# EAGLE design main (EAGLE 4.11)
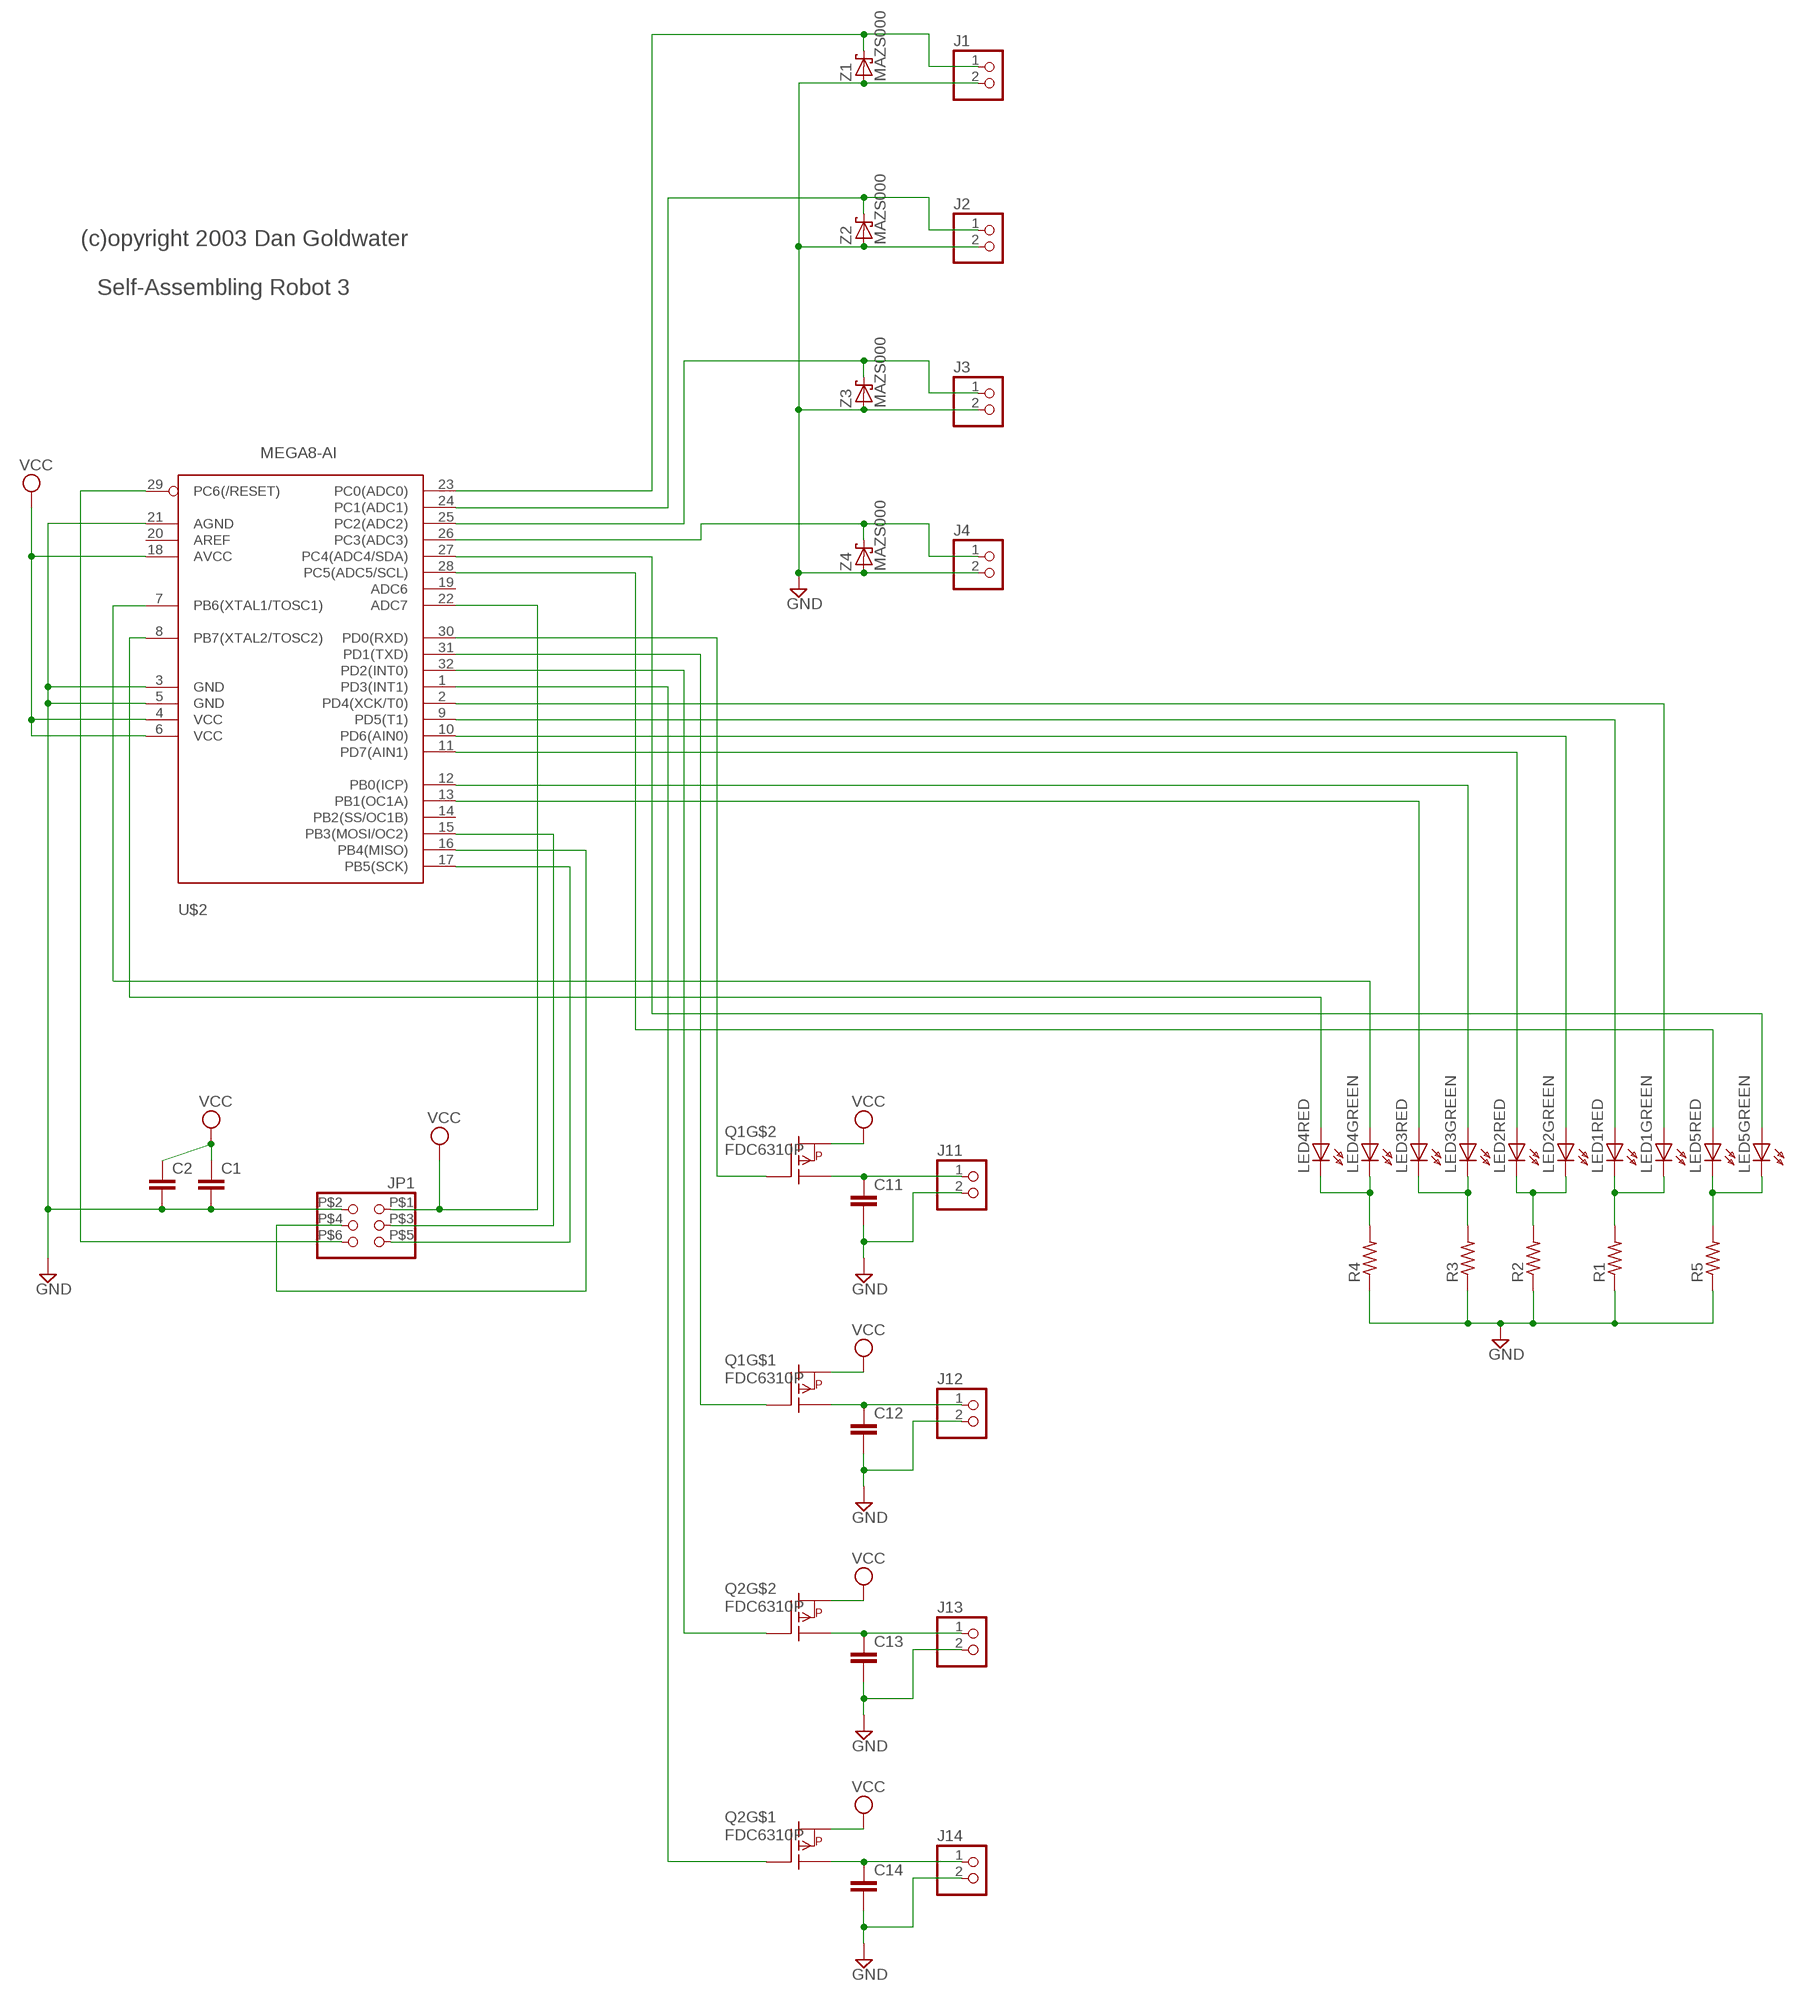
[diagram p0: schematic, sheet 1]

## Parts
C1  C-EUC0603  [C0603]
C2  C-EUC0603  [C0603]
C11  C-EUC0603  [C0603]
C12  C-EUC0603  [C0603]
C13  C-EUC0603  [C0603]
C14  C-EUC0603  [C0603]
J1  PINHD-1X2  [1X02]
J2  PINHD-1X2  [1X02]
J3  PINHD-1X2  [1X02]
J4  PINHD-1X2  [1X02]
J11  PINHD-1X2  [1X02]
J12  PINHD-1X2  [1X02]
J13  PINHD-1X2  [1X02]
J14  PINHD-1X2  [1X02]
JP1  PINHD-2X3SMT  [HIROSE_A3-6PA-2SV]
LED1  LTST-C195KGJRKT  [0605_4PIN]
LED2  LTST-C195KGJRKT  [0605_4PIN]
LED3  LTST-C195KGJRKT  [0605_4PIN]
LED4  LTST-C195KGJRKT  [0605_4PIN]
LED5  LTST-C195KGJRKT  [0605_4PIN]
Q1  FDC6310P  [SUPERSOT6]
Q2  FDC6310P  [SUPERSOT6]
R1  R-US_R0603  [R0603]
R2  R-US_R0603  [R0603]
R3  R-US_R0603  [R0603]
R4  R-US_R0603  [R0603]
R5  R-US_R0603  [R0603]
U$2  MEGA8-AI  [TQFP32-08]
Z1  MAZS000  [SSMINI2-F1]
Z2  MAZS000  [SSMINI2-F1]
Z3  MAZS000  [SSMINI2-F1]
Z4  MAZS000  [SSMINI2-F1]

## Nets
GND [power]: C1.2 C2.2 C11.2 C12.2 C13.2 C14.2 J1.2 J2.2 J3.2 J4.2 J11.2 J12.2 J13.2 J14.2 JP1.P$2 R1.1 R2.1 R3.1 R4.1 R5.1 U$2.3(GND) U$2.5(GND) U$2.21(AGND) Z1.A Z2.A Z3.A Z4.A
N$1: LED5.2(RED:A) U$2.28(PC5(ADC5/SCL))
N$2: J2.1 U$2.24(PC1(ADC1)) Z2.C
N$3: J3.1 U$2.25(PC2(ADC2)) Z3.C
N$4: J4.1 U$2.26(PC3(ADC3)) Z4.C
N$5: LED3.2(RED:A) U$2.13(PB1(OC1A))
N$6: JP1.P$6 U$2.29(PC6(/RESET))
N$7: JP1.P$5 U$2.17(PB5(SCK))
N$8: JP1.P$4 U$2.16(PB4(MISO))
N$9: C11.1 J11.1 Q1.4(DP)
N$10: Q1.3(GP) U$2.30(PD0(RXD))
N$11: LED2.3(GREEN:C) LED2.4(RED:C) R2.2
N$12: LED2.1(GREEN:A) U$2.10(PD6(AIN0))
N$13: LED1.2(RED:A) U$2.9(PD5(T1))
N$14: JP1.P$3 U$2.15(PB3(MOSI/OC2))
N$15: LED3.1(GREEN:A) U$2.12(PB0(ICP))
N$16: LED1.3(GREEN:C) LED1.4(RED:C) R1.2
N$17: LED4.3(GREEN:C) LED4.4(RED:C) R4.2
N$18: LED4.2(RED:A) U$2.8(PB7(XTAL2/TOSC2))
N$19: LED4.1(GREEN:A) U$2.7(PB6(XTAL1/TOSC1))
N$20: C12.1 J12.1 Q1.6(DP)
N$21: LED3.3(GREEN:C) LED3.4(RED:C) R3.2
N$22: C13.1 J13.1 Q2.4(DP)
N$23: LED2.2(RED:A) U$2.11(PD7(AIN1))
N$24: C14.1 J14.1 Q2.6(DP)
N$25: J1.1 U$2.23(PC0(ADC0)) Z1.C
N$26: LED5.1(GREEN:A) U$2.27(PC4(ADC4/SDA))
N$27: LED5.3(GREEN:C) LED5.4(RED:C) R5.2
N$28: Q1.1(GP) U$2.31(PD1(TXD))
N$29: Q2.3(GP) U$2.32(PD2(INT0))
N$30: Q2.1(GP) U$2.1(PD3(INT1))
N$31: LED1.1(GREEN:A) U$2.2(PD4(XCK/T0))
VCC [power]: C1.1 C2.1 JP1.P$1 Q1.2(SP) Q1.5(SP) Q2.2(SP) Q2.5(SP) U$2.4(VCC) U$2.6(VCC) U$2.18(AVCC) U$2.22(ADC7)
Unconnected: U$2.14(PB2(SS/OC1B)) U$2.19(ADC6) U$2.20(AREF)

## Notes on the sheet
- (c)opyright 2003 Dan Goldwater
- Self-Assembling Robot 3

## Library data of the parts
C1 C2 C11-C14 = proj:C-EU: CAPACITOR, European symbol
J1-J4 J11-J14 = proj:PINHD-1X2: 2mm PIN HEADER
JP1 = proj:PINHD-2X3: 2mm PIN HEADER
LED1-LED5 = proj:LTST-C195KGJRKT: Lite-On 0605 dual LED
Q1 Q2 = proj:FDC6310P
R1-R5 = proj:R-US_: RESISTOR, American symbol
U$2 = proj:MEGA8: MICROCONTROLLER 8 Kbytes FLASH 1 kbytes SRAM 512 bytes EEPROM USART 6-channel 10 bit ADC 2-channel 8 bit ADC
Z1-Z4 = proj:MAZS000: Panasonic Zener Diode

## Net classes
0 default: width 0.178 mm, drill 0.178 mm, clearance 0.381 mm
1 power: width 0.254 mm, drill 0.178 mm, clearance 0.381 mm

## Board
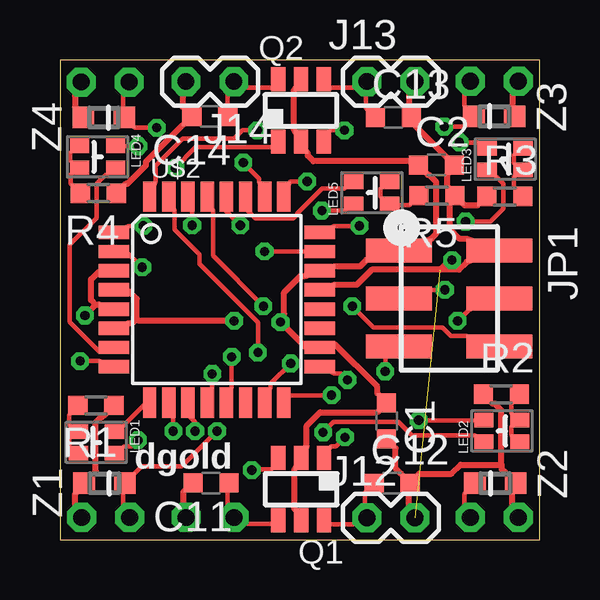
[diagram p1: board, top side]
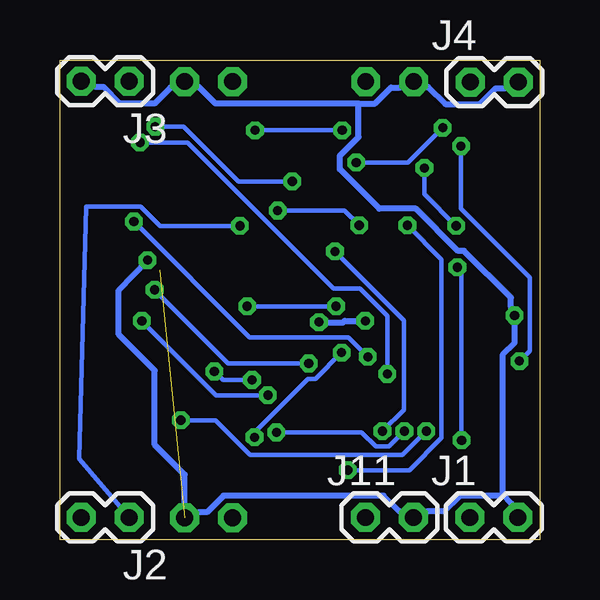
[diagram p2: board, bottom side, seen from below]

Size 20 x 20 mm. Coordinates in mm from the lower left corner, seen from the top.
Outline: 0,0 20,0 20,20 0,20 0,0
Copper layers (1*16): Top 0.035mm / dielectric 1.5mm / Bottom 0.035mm
Design rules "default": minimum track width 7mil, minimum drill 13mil, track to track 7mil, track to pad 7mil, pad to pad 7mil, via to via 7mil, smd to smd 5mil, copper to edge 10mil, drill to drill 7mil, minimum pad ring 10mil, minimum via ring 7mil, stop-mask expansion 0.5mil, vias tented up to drill 16mil, thermal gap 10mil

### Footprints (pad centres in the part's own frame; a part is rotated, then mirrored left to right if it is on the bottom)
C0603 = smd 0.8 x 0.8: 1 -0.75,0; 2 0.75,0
1X02 = drill 0.7 octagon: 1 -1,0; 2 1,0
HIROSE_A3-6PA-2SV = smd 1 x 2.75: P$1 -2,-2.1; P$2 -2,2.1; P$3 0,-2.1; P$4 0,2.1; P$5 2,-2.1; P$6 2,2.1
0605_4PIN = smd 0.6 x 0.8: 1 0.45,0.75; 2 -0.45,0.75; 3 0.45,-0.75; 4 -0.45,-0.75
SUPERSOT6 = smd 0.6 x 1: 1 -0.95,-1.3; 2 0,-1.3; 3 0.95,-1.3; 4 0.95,1.3; 5 0,1.3; 6 -0.95,1.3
R0603 = smd 0.8 x 0.8: 1 -0.75,0; 2 0.75,0
TQFP32-08 = smd 1.27 x 0.559: 1 -4.293,2.8; 2 -4.293,2; 3 -4.293,1.2; 4 -4.293,0.4; 5 -4.293,-0.4; 6 -4.293,-1.2; 7 -4.293,-2; 8 -4.293,-2.8; 17 4.293,-2.8; 18 4.293,-2; 19 4.293,-1.2; 20 4.293,-0.4; 21 4.293,0.4; 22 4.293,1.2; 23 4.293,2; 24 4.293,2.8 | smd 0.559 x 1.27: 9 -2.8,-4.293; 10 -2,-4.293; 11 -1.2,-4.293; 12 -0.4,-4.293; 13 0.4,-4.293; 14 1.2,-4.293; 15 2,-4.293; 16 2.8,-4.293; 25 2.8,4.293; 26 2,4.293; 27 1.2,4.293; 28 0.4,4.293; 29 -0.4,4.293; 30 -1.2,4.293; 31 -2,4.293; 32 -2.8,4.293
SSMINI2-F1 = smd 0.9 x 0.9: A 0,0.85; C 0,-0.85

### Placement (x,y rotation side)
C1  13.61,4.95 270 top
C2  15.7,15.61 0 top
C11  6.3,2.36 180 top
C12  13.85,2.35 0 top
C13  13.9,17.6 0 top
C14  6.25,17.65 180 top
J1  1.91,0.92 0 bottom
J2  18.11,0.92 180 bottom
J3  18.11,19.12 180 bottom
J4  1.89,19.08 0 bottom
J11  6.26,0.92 0 bottom
J12  13.8,0.9 0 top
J13  13.8,19.1 0 top
J14  6.25,19.1 180 top
JP1  16.23,10.06 270 top
LED1  1.52,4.05 270 top
LED2  18.43,4.53 90 top
LED3  18.56,15.86 90 top
LED4  1.57,15.96 270 top
LED5  13,14.46 90 top
Q1  10.06,2.1 180 top
Q2  10.05,17.9 0 top
R1  1.5,5.59 180 top
R2  18.4,6.06 0 top
R3  18.55,14.31 0 top
R4  1.6,14.44 180 top
R5  15.72,14.34 180 top
U$2  6.54,10.01 0 top
Z1  1.86,2.35 90 top
Z2  18.15,2.35 270 top
Z3  18.11,17.65 270 top
Z4  1.83,17.6 90 top

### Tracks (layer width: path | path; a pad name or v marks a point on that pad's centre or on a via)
GND  (via drill 0.38)  (1 unrouted)
  Top 0.254: U$2.21 11.46,10.62 12.37,10.62 13.01,11.25 16.64,11.25 16.97,11.58 JP1.P$2 16.97,12.55 16.66,12.55 16.23,12.98 16.23,13.95 R5.1 | Z4.A 0.64,18.03 0.64,18.49 J4.2 | R4.1 2.74,14.83 2.82,14.83 3.58,15.6 3.58,15.75 5.11,17.27 C14.2 5.11,18.03 5.11,18.52 J14.2 | Z3.A 18.87,18.09 18.87,18.52 J3.2 | R5.1 16.13,14.73 16.13,15.21 C2.2 16.05,16 14.83,17.22 C13.2 14.55,17.98 14.55,18.52 J13.2 | R3.1 17.42,13.95 16.87,13.95 R5.1 | C12.2 14.55,1.96 14.55,1.5 J12.2 | C1.2 13.99,3.81 13.99,2.97 14.22,2.74 C12.2 | 18.41,3.12 18.41,2.95 18.57,2.79 Z2.A 18.85,1.91 18.85,1.5 J2.2 | 18.41,3.12 18.41,5.38 18.14,5.66 18.03,5.66 R2.1 | C12.2 14.99,2.74 16.33,2.74 16.71,3.12 18.41,3.12 | C11.2 5.16,1.98 5.16,1.5 J11.2 | R1.1 1.85,5.21 1.75,5.11 1.73,5.11 1.5,4.88 1.5,2.85 1.45,2.79 Z1.A 0.64,1.91 0.64,1.5 J1.2 | 1.47,9.8 1.63,9.8 U$2.5 | 1.47,9.8 1.29,9.98 1.29,10.85 1.63,11.18 U$2.3 | v1.04,9.35 1.4,9.7 1.47,9.8 | v16.35,11.65 16.25,11.65 15.85,11.25
  Bottom 0.254: J4.2 1.47,18.82 1.83,18.82 2.49,18.16 3.94,18.16 4.65,18.87 J14.2 5.84,18.85 6.2,18.85 6.86,18.19 7.54,18.19 | J3.2 18.52,18.87 18.19,18.87 17.5,18.19 16.05,18.19 15.39,18.85 J13.2 14.2,18.87 13.51,18.19 7.54,18.19 | 1.52,1.85 1.52,7.72 1.04,8.2 v1.04,9.35 1.19,9.7 1.19,10.08 3.15,12.04 3.4,12.04 5.16,13.79 6.68,13.79 8.33,15.44 8.33,16 7.54,16.79 7.54,18.19 | 1.52,1.85 1.17,1.5 J1.2 | 1.52,1.85 1.63,1.83 3.33,1.83 3.99,1.17 4.67,1.17 J11.2 5.84,1.17 6.5,1.83 13.18,1.83 13.87,1.14 14.2,1.14 J12.2 14.8,2.7 16.05,3.95 16.05,7.05 17.55,8.55 17.55,10.4 v16.35,11.65
N$1  (via drill 0.38)
  Top 0.178: v10.92,13.72 11.86,13.72 LED5.2 | v7.52,13.11 6.93,13.69 U$2.28
  Bottom 0.178: v10.92,13.72 8.13,13.72 v7.52,13.11
N$2  (via drill 0.38)
  Top 0.178: Z2.C 16.87,1.91 16.87,1.5 J2.1 | v12.5,13.08 11.46,13.08 U$2.24
  Bottom 0.178: v12.5,13.08 15.82,13.08 16.64,13.89 17.2,13.89 18.9,13.89 19.2,3.37 J2.1
N$3  (via drill 0.38)
  Top 0.178: J3.1 16.87,18.52 16.87,18.09 Z3.C 16.82,17.22 v16.03,17.22 | v10.31,14.94 9.6,14.94 U$2.25
  Bottom 0.178: v10.31,14.94 12.55,14.94 14.83,17.22 v16.03,17.22
N$4  (via drill 0.38)
  Top 0.178: J4.1 2.64,18.49 2.64,18.03 Z4.C 3.12,17.17 v4.04,17.17 | v7.64,15.72 8.31,15.06 8.31,14.94 U$2.26
  Bottom 0.178: v7.64,15.72 5.49,15.72 v4.04,17.17
N$5  (via drill 0.38)
  Top 0.178: v16.92,13.26 17.96,13.26 18.49,13.79 18.49,14.83 18.21,15.11 LED3.2 | v7.16,7.62 7.16,6.35 U$2.13
  Bottom 0.178: v16.92,13.26 12.09,8.43 7.98,8.43 v7.16,7.62
N$6  (via drill 0.38)
  Top 0.178: v8.48,9.73 6.38,11.84 6.38,13.69 U$2.29 | v12.19,9.73 13.08,8.84 15.95,8.84 16.31,8.48 16.97,8.48 JP1.P$6
  Bottom 0.178: v8.48,9.73 v12.19,9.73
N$7  (via drill 0.38)
  Top 0.178: v11.99,6.66 11.71,6.93 11.46,6.93 U$2.17 | v13.56,7.01 13.56,7.57 JP1.P$5
  Bottom 0.178: v11.99,6.66 13.21,6.66 v13.56,7.01
N$8  (via drill 0.38)
  Top 0.178: v11.33,6.02 9.6,6.02 U$2.16 | v16.59,9.12 17.04,9.58 JP1.P$4
  Bottom 0.178: v11.33,6.02 13.49,6.02 v16.59,9.12
N$9
  Top 0.178: C11.1 6.99,1.98 6.99,1.5 J11.1 7.85,0.66 8.81,0.66 Q1.4
N$10  (via drill 0.38)
  Top 0.178: v8,2.9 8.03,2.92 8.81,2.92 Q1.3 | v5.51,13.11 5.51,13.69 U$2.30
  Bottom 0.178: v8,2.9 5.44,2.9 4.09,4.24 4.09,11.68 v5.51,13.11
N$11
  Top 0.178: LED2.4 18.82,4.37 18.82,4.7 LED2.3 18.82,5.26 18.82,5.66 R2.2
N$12  (via drill 0.38)
  Top 0.178: v14.96,4.98 17.3,4.98 LED2.1 | v4.72,4.52 4.72,5.11 U$2.10
  Bottom 0.178: v14.96,4.98 13.51,4.98 12.06,3.53 5.71,3.53 v4.72,4.52
N$13
  Top 0.178: LED1.2 2.67,4.78 3.48,5.59 U$2.9
N$14  (via drill 0.38)
  Top 0.178: v9.63,7.34 8.79,6.5 8.79,6.35 U$2.15 | v16.05,10.41 15.49,10.41 JP1.P$3
  Bottom 0.178: v9.63,7.34 12.98,7.34 v16.05,10.41
N$15  (via drill 0.38)
  Top 0.178: v16.66,16.56 17.42,16.56 LED3.1 | v6.35,6.91 6.35,6.35 U$2.12
  Bottom 0.178: v16.66,16.56 14.68,16.56 8.59,10.46 7.49,10.46 6.35,9.32 v6.35,6.91
N$16
  Top 0.178: LED1.3 0.38,3.89 0.38,4.22 LED1.4 0.38,4.78 0.38,5.21 R1.2
N$17
  Top 0.178: R4.2 0.46,14.83 0.46,15.21 LED4.3 0.43,15.8 0.43,16.13 LED4.4
N$18  (via drill 0.38)
  Top 0.178: v3.28,16.41 2.72,16.41 LED4.2 | v0.84,7.44 1.63,7.44 U$2.8
  Bottom 0.178: v3.28,16.41 3.28,13.79 0.41,10.92 0.41,7.87 v0.84,7.44
N$19
  Top 0.178: LED4.1 1.93,15.21 1.83,15.11 1.8,15.11 1.52,14.83 1.52,13.41 0.41,12.29 0.41,9.07 1.63,7.85 U$2.7
N$20
  Top 0.178: C12.1 12.72,1.96 12.72,1.5 J12.1 12.22,0.64 11.3,0.64 Q1.6
N$21
  Top 0.178: R3.2 18.92,14.71 18.92,15.11 LED3.4 18.92,15.7 18.92,16.03 LED3.3
N$22
  Top 0.178: C13.1 12.75,17.98 12.75,18.52 J13.1 12.22,18.85 11.28,18.85 Q2.4
N$23  (via drill 0.38)
  Top 0.178: v10.97,4.47 11.4,4.9 14.12,4.9 14.68,4.34 17.3,4.34 LED2.2 | v5.64,4.52 5.64,4.9 5.44,5.11 U$2.11
  Bottom 0.178: v10.97,4.47 7.42,4.47 6.83,3.89 6.27,3.89 v5.64,4.52
N$24
  Top 0.178: C14.1 6.99,18.03 6.99,18.52 J14.1 7.85,18.85 8.81,18.85 Q2.6
N$25  (via drill 0.38)
  Top 0.178: J1.1 2.64,1.5 2.64,1.91 Z1.C 3.15,2.79 3.4,3.05 5.08,3.05 v6.55,4.52 | v8.53,12.01 10.21,12.01 U$2.23
  Bottom 0.178: v8.53,12.01 5.66,9.14 5.66,5.41 v6.55,4.52
N$26
  Top 0.178: LED5.1 11.86,14.63 10.92,14.63 9.91,13.61 9.91,13.56 9.73,13.39 8.15,13.39 7.85,13.69 U$2.27
N$27
  Top 0.178: LED5.3 13.36,14.63 13.36,14.3 LED5.4 14.15,13.95 14.58,13.95 R5.2
N$28  (via drill 0.38)
  Top 0.178: v11.89,4.27 11.51,3.89 11.3,3.89 Q1.1 | v8.26,7.8 8.26,9.04 5.82,11.48 5.82,11.89 4.78,12.93 4.78,13.69 U$2.31
  Bottom 0.178: v11.89,4.27 11.89,4.47 9.65,6.71 9.35,6.71 v8.26,7.8
N$29  (via drill 0.38)
  Top 0.178: v11.86,17.07 11.28,17.07 Q2.3 | v8.23,17.07 7.62,17.07 7.26,16.71 5.11,16.71 3.99,15.6 3.99,14.94 U$2.32
  Bottom 0.178: v8.23,17.07 v11.86,17.07
N$30  (via drill 0.38)
  Top 0.178: v4.8,15.49 5.66,16.36 8.81,16.36 Q2.1 | v3.48,13.08 2.87,13.08 U$2.1
  Bottom 0.178: v4.8,15.49 4.8,14.4 v3.48,13.08
N$31  (via drill 0.38)
  Top 0.178: v3.25,4.14 3,3.89 2.67,3.89 LED1.1 | v3.43,11.35 2.87,11.91 U$2.2
  Bottom 0.178: v3.25,4.14 3.25,11.18 v3.43,11.35
VCC  (via drill 0.38)
  Top 0.254: Q2.5 9.75,18.72 9.75,17.09 Q2.2 10.34,16.1 10.34,16 10.57,15.77 14.55,15.77 C2.1 15.34,15.21 15.39,15.21 15.7,14.91 15.7,12.75 15.49,12.55 JP1.P$1 12.78,11.66 12.52,11.4 11.46,11.4 U$2.22 10.21,11 10.03,11 9.35,10.31 9.35,9.42 v9.2,9.07 10.21,8.05 U$2.18 11.46,8.15 13.23,6.38 13.23,6.1 C1.1 13.23,5.31 10.85,5.31 10.29,4.75 10.29,3.89 Q1.2 9.78,2.92 9.78,1.29 Q1.5 | 3.2,9.2 3.02,9.02 2.87,9.02 U$2.6 | 3.2,9.2 3.2,10.03 2.87,10.36 U$2.4 | v7.26,9.12 3.3,9.12 3.2,9.2
  Bottom 0.254: v7.26,9.12 8.13,9.12 8.2,9.04 9.17,9.04 v9.2,9.07

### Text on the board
tPlace: dgold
